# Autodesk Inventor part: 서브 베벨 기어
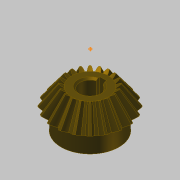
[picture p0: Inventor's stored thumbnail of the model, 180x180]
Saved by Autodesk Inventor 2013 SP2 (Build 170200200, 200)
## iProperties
Created: 2016-04
Part Number: 서브 베벨 기어
Material: 강철, 탄소
Document SubType Name: Modeling
Designer: mdu
Categories: <?xml version="1.0" encoding="UTF-16"?> <MemberInstance><Categories><FamilyTemplate><FamilyTemplateParameter ValueType="xs:double" Id="1" ObjectReferenceKey="da
Mass: 135.037 g
Surface Area: 63.6518 cm^2
Volume: 17.1585 cm^3
Density: 7.87 g/cm^3
CustomPartVersion: 1
Author: mdu
Revision Number: 1
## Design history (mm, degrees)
node "맨 위 점"
node "메쉬 평면2"
sketch "톱니 본체 스케치"
  geometry: L1 (0, 0)-(18.003, -31.331); L2 (18.003, -31.331)-(21.664, -28.891); L3 (21.664, -28.891)-(0, 0); L4 (20, -30)-(0, 0); L5 (10.813, -18.818)-(13.012, -17.352); L6 (18.003, -31.331)-(10.813, -18.818); L7 (21.664, -28.891)-(13.012, -17.352); L8 (0, -39.387)-(0, 6.564) reference; L9 (0, -30)-(21.664, -30)
  constraints: 16 end point, 4 point on line, 3 perpendicular, 2 collinear, 1 horizontal alignment, 1 vertical alignment
  dimensions: "d0" = 40 diameter of L4.start L8 (= da_de); "d1" = 36.00616 diameter of L1.end L8 (= da_dfe); "d2" = 43.3282 diameter of L2.end L8 (= da_dae); "d3" = 14.4 distance between parallel lines of L2 L5 (= da_b); "d4" = 28.8906 vertical distance of L2.end L1.start (= da_ve)
revolve "톱니 본체" sketch "톱니 본체 스케치" stored, may be unused: angle "d5" = 90 deg
node "시작점"
node "톱니 평면"
sketch "시작 스케치"
  geometry: L1 (0, -23.505)-(0, 10.645) reference; L2 (-0.834, -2.928)-(0.834, -2.928); A1 r 8.898 centre (-9.698, -3.713) between (-0.834, -2.928) and (-3.903, 3.04); A2 r 8.898 centre (9.698, -3.713) between (3.903, 3.04) and (0.834, -2.928); A3 r 27.357 centre (0, -24.037) between (3.903, 3.04) and (-3.903, 3.04); 1 further point
  constraints: 6 point on circle, 3 centre point, 3 symmetric about line, 2 end point, 1 coincident, 1 perpendicular, 1 other
  dimensions: "d7" = 8.89846 radius of A1 (= fd_rr); "d8" = 9.69794 horizontal distance of point (0, -24.037) A1.centre (= fd_x); "d9" = 20.32439 vertical distance of point (0, -24.037) A1.centre (= fd_y); "d57" = 27.35701 radius of A3 (= 0.5 x fd_dva + 0.3 x da_he); "d58" = 21.10901 distance from line of A3.centre L2 (= 0.5 x fd_dva - 1.12 x da_he)
node "끝점"
  node "끝 평면"
sketch "3D 스케치 오른쪽"
  node "Helical Curve Right" dims "d65" = 229.90621 (computed from da_dm, da_delta, da_beta), "d66" = 31.5, "d67" = 40 (= da_de), "d68" = -5.88003 (= -da_delta), "d69" = 12.16458 (computed from fd_loft, da_delta)
node "끝 평면 오른쪽"
sketch "끝 스케치 오른쪽"
  geometry: L1 (0, -22.649)-(0, 12.15) reference; L2 (-0.497, -1.72)-(0.497, -1.72); A1 r 5.299 centre (-5.775, -2.187) between (-0.497, -1.72) and (-2.324, 1.834); A2 r 5.299 centre (5.775, -2.187) between (2.324, 1.834) and (0.497, -1.72); A3 r 16.291 centre (0, -14.29) between (2.324, 1.834) and (-2.324, 1.834); 1 further point
  constraints: 6 point on circle, 3 centre point, 3 symmetric about line, 2 end point, 1 coincident, 1 perpendicular, 1 other
  dimensions: "d70" = 5.77526 horizontal distance of A3.centre A1.centre (computed from fd_x, fd_ratio); "d71" = 12.10346 vertical distance of point (0, -14.29) A1.centre (computed from fd_y, fd_ratio); "d72" = 5.29916 radius of A1 (computed from fd_rr, fd_ratio); "d73" = 12.57071 distance from line of point (0, -14.29) L2 (computed from d58, fd_ratio); "d74" = 16.29149 radius of A3 (computed from d57, fd_ratio)
feature "로프트 오른쪽" sketch "끝 스케치 오른쪽" dims "d75" = 0, "d77" = 0, "d79" = 0, "d80" = 90 deg, "d85" = 20, "d92" = 90 deg, "d93" = 90 deg, "da_teethtype" = 0 [user parameter]
sketch "3D 스케치 왼쪽"
  node "Helical Curve Left" dims "d26" = 229.90621 (computed from da_dm, da_delta, da_beta), "d27" = 12.16458 (computed from fd_loft, da_delta), "d28" = 40 (= da_de), "d29" = -5.88003 (= -da_delta)
node "끝 평면 왼쪽"
sketch "끝 스케치 왼쪽" dims "d56" = 10.82768 (derived)
  geometry: L1 (0, -35.087)-(0, 18.089) reference; L2 (-0.497, -1.716)-(0.497, -1.716); A1 r 5.299 centre (-5.775, -2.183) between (-0.497, -1.716) and (-2.324, 1.838); A2 r 5.299 centre (5.775, -2.183) between (2.324, 1.838) and (0.497, -1.716); A3 r 16.291 centre (0, -14.287) between (2.324, 1.838) and (-2.324, 1.838); 2 further points; 1 other entity
  constraints: 6 point on circle, 3 centre point, 3 symmetric about line, 2 end point, 1 coincident, 2 other
  dimensions: "d30" = 5.29916 radius of A1 (computed from fd_rr, fd_ratio); "d31" = 5.77526 horizontal distance of point (0, -14.287) A1.centre (computed from fd_x, fd_ratio); "d32" = 12.10346 vertical distance of A1.centre point (0, -14.287) (computed from fd_y, fd_ratio); "d61" = 16.29149 radius of A3 (computed from d57, fd_ratio); "d62" = 12.57071 distance from line of point (0, -14.287) L2 (computed from d58, fd_ratio)
feature "로프트 왼쪽" sketch "끝 스케치 왼쪽" dims "d35" = 0, "d37" = 0, "d39" = 0, "d40" = 90 deg, "d84" = 10, "d90" = 90 deg, "d91" = 90 deg, "da_teethtype" = 0 [user parameter]
sketch "본체 스케치"
  geometry: L1 (0, -35.038)-(0, -19.531) reference; L2 (18.003, -31.331)-(10.813, -18.818) reference; L3 (10.813, -18.818)-(0, -18.818); L4 (18.003, -31.331)-(0, -31.331)
  constraints: 4 end point, 2 perpendicular, 2 point on line
revolve "본체 고정" sketch "본체 스케치" stored, may be unused: angle "d46" = 90 deg
feature "피치 지름" dims angle "d47" = 90 deg
sketch "스케치8"
  geometry: C1 r 17 at (0, 0); 1 further point
  constraints: 1 centre point, 1 coincident
  dimensions: "d94" = 34 diameter of C1
extrude "돌출1" join sketch "스케치8" distance "d95" = 10; taper "d96" = 0 deg
sketch "스케치9"
  geometry: 1 further point
hole "구멍1" sketch "스케치9" at (0, 0) diameter "d97" = 12; stored, may be unused: countersink angle "d101" = 90 deg, drill point angle "d103" = 118 deg; dims "d98" = 6, "d99" = 4, "d100" = 2, "d102" = 8
sketch "스케치10"
  geometry: 1 further point
sketch "스케치11"
  geometry: 1 further point
sketch "스케치12"
  geometry: L1 (-2, 5.657)-(-2, 7.8); L2 (-2, 7.8)-(2, 7.8); L3 (2, 7.8)-(2, 5.657); A1 r 6 centre (0, 0) between (-2, 5.657) and (2, 5.657) reference; 1 further point
  constraints: 6 end point, 2 parallel, 2 point on circle, 1 perpendicular, 1 vertical
  dimensions: "d104" = 4 distance of L1.end L2.end; "d105" = 13.8 dimension on A1 L2
extrude "돌출2" cut sketch "스케치12" stored distance "d106" = 7; taper "d107" = 0 deg
chamfer "모따기1" distance "d108" = 1; stored, may be unused: second distance "d109" = 2, angle "d110" = 45 deg
body "Solid1"
feature "로프트" dims "d17" = 0, "d18" = 90 deg, "d19" = 0, "d20" = 90 deg, "d89" = 0, "da_teethtype" = 0 [user parameter]
pattern_circular "원형 패턴" dims angle "d22" = 360 deg, "d88" = 0, "da_teethtype" = 0 [user parameter]
pattern_circular "원형 패턴 오른쪽" dims angle "d82" = 360 deg, "da_teethtype" = 0 [user parameter]
pattern_circular "원형 패턴 왼쪽" dims angle "d42" = 360 deg, "da_teethtype" = 0 [user parameter]
sketch "끝 스케치"
  geometry: L1 (0, -15.359)-(0, 6.983) reference; L2 (-0.497, -1.72)-(0.497, -1.72); A1 r 5.299 centre (-5.775, -2.187) between (-0.497, -1.72) and (-2.324, 1.834); A2 r 5.299 centre (5.775, -2.187) between (2.324, 1.834) and (0.497, -1.72); A3 r 16.291 centre (0, -14.29) between (2.324, 1.834) and (-2.324, 1.834); 1 further point
  constraints: 6 point on circle, 3 centre point, 3 symmetric about line, 2 end point, 1 coincident, 1 other
  dimensions: "d12" = 5.29916 radius of A1 (computed from fd_rr, fd_ratio); "d15" = 5.77526 horizontal distance of A1.centre point (0, -14.29) (computed from fd_x, fd_ratio); "d16" = 12.10346 vertical distance of A1.centre point (0, -14.29) (computed from fd_y, fd_ratio); "d59" = 16.29149 radius of A3 (computed from d57, fd_ratio); "d60" = 12.57071 distance from line of A3.centre L2 (computed from d58, fd_ratio)
sketch "Sketch6"
  geometry: L1 (20, -30)-(0, 0) reference; L2 (0, -37.8)-(0, 6.3) reference
body "Srf1"
other parameters: "da_b" = 14.4 [user parameter; used in 2 equation terms], "da_de" = 40 [user parameter; used in 4 equation terms], "da_dae" = 43.3282 [user parameter; used in 2 equation terms], "da_dfe" = 36.00616 [user parameter; used in 1 equation term], "da_le" = 36.05551 [user parameter; used in 1 equation term], "da_omega" = 90 deg [user parameter; used in 1 equation term], "da_beta" = 0 [user parameter; used in 2 equation terms], "da_delta" = 5.88003 [user parameter; used in 8 equation terms], "da_alpha" = 20 deg [user parameter; used in 2 equation terms], "da_he" = 4.4 [user parameter; used in 4 equation terms], "da_ve" = 28.8906 [user parameter; used in 1 equation term], "fd_dv" = 48.07402 (computed from da_de, da_delta) [user parameter; used in 1 equation term], "fd_dva" = 52.07402 (computed from da_dae, da_delta) [user parameter; used in 3 equation terms], "fd_dvb" = 45.1748 (computed from fd_dv, da_alpha) [user parameter; used in 2 equation terms], "da_zv" = 240.37008 [user parameter; used in 1 equation term], "fd_loft" = 14.62 (= da_b + 0.05 x da_he) [user parameter; used in 4 equation terms], "fd_ratio" = 5.95514 (computed from da_le, fd_loft) [user parameter; used in 15 equation terms], "fd_rr" = 8.89846 (computed from fd_dd, fd_dvb) [user parameter; used in 6 equation terms], "fd_angle" = 0.66075 (computed from da_zv) [user parameter; used in 4 equation terms], "fd_x1" = 1.58709 (computed from da_dvw, fd_angle) [user parameter; used in 1 equation term], "fd_y1" = 23.98456 (computed from da_dvw, fd_angle) [user parameter; used in 1 equation term], "fd_x2" = 8.11084 (computed from fd_rr, fd_angle2, fd_angle) [user parameter; used in 1 equation term], "fd_y2" = 3.66016 (computed from fd_rr, fd_angle2, fd_angle) [user parameter; used in 1 equation term], "fd_x" = 9.69794 (= fd_x1 + fd_x2) [user parameter; used in 4 equation terms], "fd_y" = 20.32439 (= fd_y1 - fd_y2) [user parameter; used in 4 equation terms], "fd_angle2" = 3.57832 (computed from fd_dvb, fd_dd, da_alpha) [user parameter; used in 2 equation terms], "fd_dd" = 48.55402 (= fd_dva - 0.8 x da_he) [user parameter; used in 2 equation terms], "da_dvw" = 48.07402 [user parameter; used in 2 equation terms], "d11" = 14.62 (= fd_loft), "da_dm" = 32.01232 [user parameter; used in 2 equation terms], "da_x" = 0 [user parameter], "da_m" = 2 [user parameter], "d48" = 0, "d49" = 0, "d50" = 90 deg (= da_omega), "d51" = 9 deg (computed from da_z), "d52" = 0, "d53" = 0, "d54" = 0
